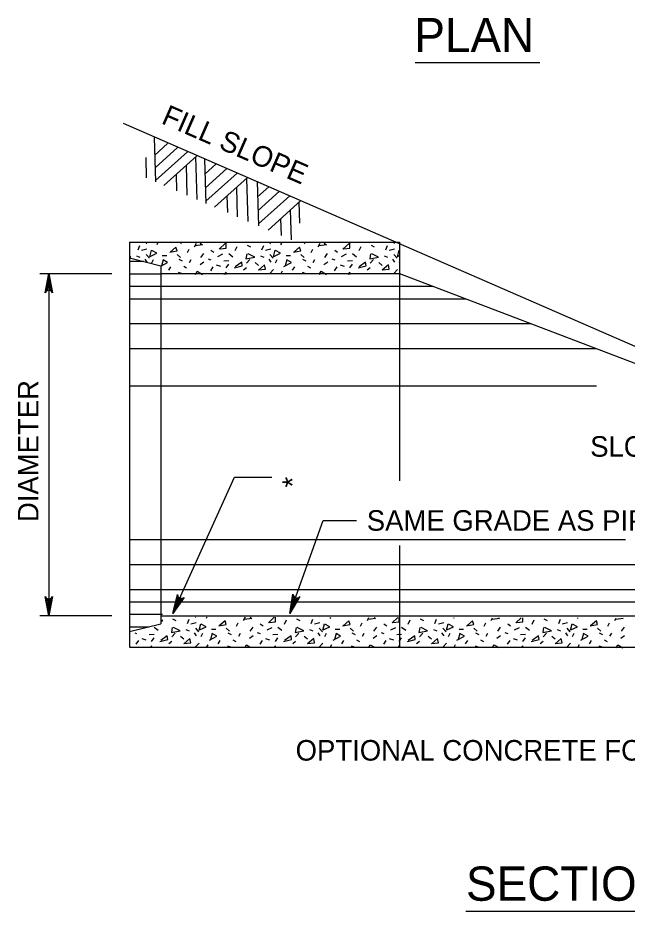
# Model space of a CAD drawing. Extents: x 1 to 8.2, y -2.1 to 8.1.
# Drawn here: x 1.257 to 3.034, y 2.836 to 5.444 of the extents above; entities that cross this region are included whole.
import ezdxf

# ---------------------------------------------------------------- set-up
doc = ezdxf.new("R2010")
doc.units = 0
for name, color, linetype in [('DETL-DIMS', 7, 'Continuous'), ('DETL-LINE', 7, 'Continuous'), ('DETL-NOTE', 7, 'Continuous'), ('DETL-PATT', 7, 'Continuous'), ('DETL-TITL', 7, 'Continuous')]:
    doc.layers.add(name, color=color, linetype=linetype)

msp = doc.modelspace()

# ---------------------------------------------------------------- linework, layer by layer
at = {"layer": 'DETL-DIMS'}
for p, q in [((1.3206, 4.6982), (1.5305, 4.6982)), ((1.347, 4.6982), (1.347, 3.6982)), ((1.7082, 3.7049), (1.8886, 4.1036)), ((1.8886, 4.1036), (1.9971, 4.1036)), ((2.0501, 3.7049), (2.147, 3.977)), ((2.147, 3.977), (2.244, 3.977)), ((1.3206, 3.6995), (1.5305, 3.6995))]:
    msp.add_line(p, q, dxfattribs=at)
for points in [[(1.347, 4.6982), (1.3576, 4.6417), (1.3545, 4.6461), (1.3508, 4.6483), (1.347, 4.649), (1.3432, 4.6483), (1.3394, 4.6461), (1.3364, 4.6417), (1.347, 4.6982), (1.3394, 4.6461), (1.3432, 4.6483), (1.347, 4.6982), (1.347, 4.649), (1.3508, 4.6483), (1.347, 4.6982), (1.3545, 4.6461)], [(1.7082, 3.7049), (1.7219, 3.7608), (1.7228, 3.7555), (1.7253, 3.7519), (1.7285, 3.7498), (1.7322, 3.7488), (1.7366, 3.7493), (1.7412, 3.752), (1.7082, 3.7049), (1.7366, 3.7493), (1.7322, 3.7488), (1.7082, 3.7049), (1.7285, 3.7498), (1.7253, 3.7519), (1.7082, 3.7049), (1.7228, 3.7555)], [(2.0501, 3.7049), (2.0591, 3.7617), (2.0605, 3.7566), (2.0633, 3.7532), (2.0666, 3.7513), (2.0704, 3.7506), (2.0747, 3.7515), (2.079, 3.7546), (2.0501, 3.7049), (2.0747, 3.7515), (2.0704, 3.7506), (2.0501, 3.7049), (2.0666, 3.7513), (2.0633, 3.7532), (2.0501, 3.7049), (2.0605, 3.7566)], [(1.347, 3.6982), (1.3364, 3.7547), (1.3394, 3.7504), (1.3432, 3.7481), (1.347, 3.7475), (1.3508, 3.7481), (1.3545, 3.7504), (1.3576, 3.7547), (1.347, 3.6982), (1.3545, 3.7504), (1.3508, 3.7481), (1.347, 3.6982), (1.347, 3.7475), (1.3432, 3.7481), (1.347, 3.6982), (1.3394, 3.7504)]]:
    msp.add_lwpolyline(points, dxfattribs=at)
at = {"layer": 'DETL-LINE'}
for p, q in [((1.5635, 5.1374), (3.9667, 4.0886)), ((1.5824, 4.7891), (2.3702, 4.7891)), ((1.5824, 4.7891), (1.5824, 4.6982)), ((1.5824, 4.7891), (1.5824, 3.6982)), ((2.3702, 4.7891), (2.3702, 4.0925)), ((1.5824, 4.7437), (1.6733, 4.7209)), ((1.5824, 4.7336), (1.6226, 4.7336)), ((1.6733, 4.7209), (1.6733, 3.6755)), ((1.5824, 4.6982), (1.5824, 4.4435)), ((1.5824, 4.6972), (1.6733, 4.6972)), ((1.6733, 4.6982), (2.3702, 4.6982)), ((2.3702, 4.6982), (3.9667, 4.0886)), ((1.5824, 4.6609), (2.468, 4.6609)), ((1.5824, 4.6245), (2.5633, 4.6245)), ((1.5824, 4.5518), (2.7537, 4.5518)), ((1.5824, 4.4791), (2.9442, 4.4791)), ((1.5824, 4.37), (2.9442, 4.37)), ((1.5824, 3.9214), (3.0294, 3.9214)), ((2.3702, 3.9039), (2.3702, 3.6073)), ((1.5824, 3.8486), (3.1805, 3.8486)), ((1.5824, 3.7759), (3.3316, 3.7759)), ((1.5824, 3.7395), (3.4222, 3.7395)), ((1.5824, 3.7032), (1.6785, 3.7032)), ((1.5824, 3.6982), (1.5824, 3.6073)), ((1.6733, 3.6982), (4.0369, 3.6982)), ((1.5824, 3.6528), (1.6733, 3.6755)), ((1.5824, 3.6668), (1.6386, 3.6668)), ((1.5824, 3.6073), (4.0369, 3.6073))]:
    msp.add_line(p, q, dxfattribs=at)
at = {"layer": 'DETL-PATT'}
for p, q in [((1.6543, 5.0948), (1.658, 4.9657)), ((1.6935, 5.078), (1.6558, 5.0438)), ((1.7219, 5.0659), (1.6571, 5.0069)), ((1.6296, 5.0372), (1.6312, 4.9771)), ((1.7514, 5.0532), (1.6584, 4.9695)), ((1.7782, 5.0418), (1.682, 4.955)), ((1.7751, 5.0391), (1.7789, 4.9139)), ((1.7473, 5.0142), (1.7497, 4.9264)), ((1.8009, 5.032), (1.8053, 4.9026)), ((1.8344, 5.0177), (1.8025, 4.9886)), ((1.7184, 4.9882), (1.7196, 4.9393)), ((1.8659, 5.0042), (1.8038, 4.948)), ((1.8966, 4.991), (1.8052, 4.9089)), ((1.9264, 4.9783), (1.8304, 4.8918)), ((1.9238, 4.9758), (1.9275, 4.8503)), ((1.9546, 4.9662), (1.9586, 4.8369)), ((1.8941, 4.9489), (1.8963, 4.8636)), ((1.989, 4.9514), (1.956, 4.9216)), ((2.0195, 4.9384), (1.9571, 4.8823)), ((1.8665, 4.9235), (1.8676, 4.8759)), ((2.0503, 4.9252), (1.9584, 4.8429)), ((2.0824, 4.9114), (1.9864, 4.825)), ((2.0765, 4.906), (2.0785, 4.845)), ((2.1, 4.9039), (2.1, 4.9039)), ((2.0508, 4.883), (2.0537, 4.7962)), ((2.0231, 4.858), (2.0242, 4.8088)), ((1.6115, 4.7785), (1.6067, 4.7665)), ((1.6325, 4.7865), (1.6308, 4.7845)), ((1.6642, 4.7865), (1.6621, 4.7821)), ((1.7305, 4.7865), (1.7331, 4.7857)), ((1.7716, 4.7761), (1.7772, 4.7865)), ((1.8625, 4.7865), (1.8438, 4.7689)), ((1.8907, 4.7653), (1.8967, 4.7773)), ((1.9256, 4.7809), (1.9352, 4.7761)), ((1.9726, 4.7785), (1.9677, 4.7665)), ((1.9936, 4.7865), (1.9918, 4.7845)), ((2.0253, 4.7865), (2.0231, 4.7821)), ((2.0915, 4.7865), (2.0941, 4.7857)), ((2.1326, 4.7761), (2.1382, 4.7865)), ((2.2235, 4.7865), (2.2048, 4.7689)), ((2.2518, 4.7653), (2.2578, 4.7773)), ((2.2867, 4.7809), (2.2963, 4.7761)), ((2.3336, 4.7785), (2.3288, 4.7665)), ((2.3546, 4.7865), (2.3528, 4.7845)), ((1.6031, 4.7496), (1.6127, 4.746)), ((1.6332, 4.7689), (1.6175, 4.7653)), ((1.6308, 4.7532), (1.6404, 4.7424)), ((1.6777, 4.7508), (1.6909, 4.7508)), ((1.721, 4.7532), (1.7307, 4.7448)), ((1.7511, 4.7592), (1.7559, 4.7689)), ((1.7981, 4.7568), (1.7896, 4.7448)), ((1.8197, 4.7665), (1.8281, 4.7604)), ((1.8534, 4.7544), (1.839, 4.7472)), ((1.8715, 4.7568), (1.8835, 4.7472)), ((1.9641, 4.7496), (1.9738, 4.746)), ((1.9942, 4.7689), (1.9786, 4.7653)), ((1.9918, 4.7532), (2.0014, 4.7424)), ((2.0387, 4.7508), (2.052, 4.7508)), ((2.0821, 4.7532), (2.0917, 4.7448)), ((2.1122, 4.7592), (2.117, 4.7689)), ((2.1591, 4.7568), (2.1507, 4.7448)), ((2.1807, 4.7665), (2.1892, 4.7604)), ((2.2144, 4.7544), (2.2, 4.7472)), ((2.2325, 4.7568), (2.2445, 4.7472)), ((2.3252, 4.7496), (2.3348, 4.746)), ((2.3552, 4.7689), (2.3396, 4.7653)), ((2.3528, 4.7532), (2.3625, 4.7424)), ((1.6272, 4.74), (1.6332, 4.7316)), ((1.6512, 4.7376), (1.6464, 4.7279)), ((1.7258, 4.74), (1.7355, 4.7352)), ((1.7571, 4.7303), (1.762, 4.7388)), ((1.7993, 4.7316), (1.7884, 4.7231)), ((1.8113, 4.7412), (1.8197, 4.7376)), ((1.8354, 4.7231), (1.8474, 4.7195)), ((1.857, 4.7352), (1.8715, 4.7364)), ((1.8642, 4.7147), (1.8715, 4.7255)), ((1.9232, 4.7279), (1.9328, 4.7388)), ((1.9485, 4.7303), (1.9581, 4.7219)), ((1.9882, 4.74), (1.9942, 4.7316)), ((2.0123, 4.7376), (2.0075, 4.7279)), ((2.0869, 4.74), (2.0965, 4.7352)), ((2.1182, 4.7303), (2.123, 4.7388)), ((2.1603, 4.7316), (2.1495, 4.7231)), ((2.1723, 4.7412), (2.1807, 4.7376)), ((2.1964, 4.7231), (2.2084, 4.7195)), ((2.2181, 4.7352), (2.2325, 4.7364)), ((2.2253, 4.7147), (2.2325, 4.7255)), ((2.2842, 4.7279), (2.2939, 4.7388)), ((2.3095, 4.7303), (2.3191, 4.7219)), ((2.3492, 4.74), (2.3552, 4.7316)), ((2.3702, 4.7315), (2.3685, 4.7279)), ((1.697, 4.7075), (1.703, 4.7171)), ((1.7246, 4.7015), (1.7331, 4.6991)), ((1.7403, 4.7195), (1.7487, 4.7147)), ((1.7941, 4.6952), (1.7941, 4.6952)), ((1.8257, 4.7171), (1.8185, 4.7063)), ((1.9148, 4.7087), (1.9232, 4.7159)), ((2.0026, 4.7099), (1.9918, 4.6979)), ((2.0279, 4.7051), (2.0231, 4.6955)), ((2.058, 4.7075), (2.064, 4.7171)), ((2.0857, 4.7015), (2.0941, 4.6991)), ((2.1013, 4.7195), (2.1097, 4.7147)), ((2.1564, 4.6954), (2.1564, 4.6954)), ((2.1564, 4.6954), (2.1564, 4.6954)), ((2.1564, 4.6954), (2.1564, 4.6954)), ((2.1564, 4.6954), (2.1564, 4.6954)), ((2.1868, 4.7171), (2.1795, 4.7063)), ((2.2758, 4.7087), (2.2842, 4.7159)), ((2.3637, 4.7099), (2.3528, 4.6979)), ((1.6769, 3.6816), (1.6792, 3.6864)), ((1.7081, 3.69), (1.7177, 3.6852)), ((1.755, 3.6876), (1.7502, 3.6755)), ((1.7767, 3.6779), (1.7611, 3.6743)), ((1.7753, 3.6948), (1.7743, 3.6936)), ((1.8073, 3.6947), (1.8056, 3.6912)), ((1.8946, 3.6683), (1.8994, 3.6779)), ((1.9151, 3.6852), (1.9201, 3.6944)), ((2.0046, 3.6942), (1.9873, 3.6779)), ((2.0342, 3.6743), (2.0402, 3.6864)), ((2.0691, 3.69), (2.0788, 3.6852)), ((2.1161, 3.6876), (2.1113, 3.6755)), ((2.1377, 3.6779), (2.1221, 3.6743)), ((2.1357, 3.694), (2.1353, 3.6936)), ((2.168, 3.6939), (2.1666, 3.6912)), ((2.2557, 3.6683), (2.2605, 3.6779)), ((2.2761, 3.6852), (2.2807, 3.6936)), ((2.3648, 3.6934), (2.3483, 3.6779)), ((2.3953, 3.6743), (2.4013, 3.6864)), ((2.4302, 3.69), (2.4398, 3.6852)), ((2.4771, 3.6876), (2.4723, 3.6755)), ((2.4988, 3.6779), (2.4831, 3.6743)), ((2.5286, 3.6931), (2.5276, 3.6912)), ((2.6167, 3.6683), (2.6215, 3.6779)), ((2.6372, 3.6852), (2.6413, 3.6928)), ((2.725, 3.6926), (2.7094, 3.6779)), ((2.7563, 3.6743), (2.7623, 3.6864)), ((2.7912, 3.69), (2.8008, 3.6852)), ((2.8381, 3.6876), (2.8333, 3.6755)), ((2.8598, 3.6779), (2.8441, 3.6743)), ((2.8892, 3.6923), (2.8887, 3.6912)), ((2.9777, 3.6683), (2.9825, 3.6779)), ((2.9982, 3.6852), (3.0019, 3.692)), ((1.6544, 3.6655), (1.666, 3.6563)), ((1.7466, 3.6587), (1.7562, 3.6551)), ((1.7743, 3.6623), (1.7839, 3.6515)), ((1.8212, 3.6599), (1.8345, 3.6599)), ((1.8645, 3.6623), (1.8742, 3.6539)), ((1.9416, 3.6659), (1.9331, 3.6539)), ((1.9632, 3.6755), (1.9717, 3.6695)), ((1.9969, 3.6635), (1.9825, 3.6563)), ((2.015, 3.6659), (2.027, 3.6563)), ((2.1076, 3.6587), (2.1173, 3.6551)), ((2.1353, 3.6623), (2.145, 3.6515)), ((2.1823, 3.6599), (2.1955, 3.6599)), ((2.2256, 3.6623), (2.2352, 3.6539)), ((2.3026, 3.6659), (2.2942, 3.6539)), ((2.3243, 3.6755), (2.3327, 3.6695)), ((2.358, 3.6635), (2.3435, 3.6563)), ((2.376, 3.6659), (2.388, 3.6563)), ((2.4687, 3.6587), (2.4783, 3.6551)), ((2.4964, 3.6623), (2.506, 3.6515)), ((2.5433, 3.6599), (2.5565, 3.6599)), ((2.5866, 3.6623), (2.5962, 3.6539)), ((2.6636, 3.6659), (2.6552, 3.6539)), ((2.6853, 3.6755), (2.6937, 3.6695)), ((2.719, 3.6635), (2.7045, 3.6563)), ((2.737, 3.6659), (2.7491, 3.6563)), ((2.8297, 3.6587), (2.8393, 3.6551)), ((2.8574, 3.6623), (2.867, 3.6515)), ((2.9043, 3.6599), (2.9176, 3.6599)), ((2.9476, 3.6623), (2.9573, 3.6539)), ((3.0247, 3.6659), (3.0162, 3.6539)), ((1.5978, 3.6485), (1.6022, 3.6466)), ((1.6082, 3.6262), (1.601, 3.6154)), ((1.6178, 3.6322), (1.6299, 3.6286)), ((1.6395, 3.6442), (1.6539, 3.6454)), ((1.6467, 3.6238), (1.6539, 3.6346)), ((1.7057, 3.637), (1.7153, 3.6479)), ((1.731, 3.6394), (1.7406, 3.631)), ((1.7707, 3.6491), (1.7767, 3.6406)), ((1.7947, 3.6466), (1.7899, 3.637)), ((1.8405, 3.6166), (1.8465, 3.6262)), ((1.8694, 3.6491), (1.879, 3.6442)), ((1.8838, 3.6286), (1.8922, 3.6238)), ((1.9007, 3.6394), (1.9055, 3.6479)), ((1.9428, 3.6406), (1.9319, 3.6322)), ((1.9548, 3.6503), (1.9632, 3.6466)), ((1.9692, 3.6262), (1.962, 3.6154)), ((1.9789, 3.6322), (1.9909, 3.6286)), ((2.0005, 3.6442), (2.015, 3.6454)), ((2.0078, 3.6238), (2.015, 3.6346)), ((2.0667, 3.637), (2.0764, 3.6479)), ((2.092, 3.6394), (2.1016, 3.631)), ((2.1317, 3.6491), (2.1377, 3.6406)), ((2.1558, 3.6466), (2.151, 3.637)), ((2.2015, 3.6166), (2.2075, 3.6262)), ((2.2304, 3.6491), (2.24, 3.6442)), ((2.2448, 3.6286), (2.2533, 3.6238)), ((2.2617, 3.6394), (2.2665, 3.6479)), ((2.3038, 3.6406), (2.293, 3.6322)), ((2.3158, 3.6503), (2.3243, 3.6466)), ((2.3303, 3.6262), (2.3231, 3.6154)), ((2.3399, 3.6322), (2.3519, 3.6286)), ((2.3616, 3.6442), (2.376, 3.6454)), ((2.3688, 3.6238), (2.376, 3.6346)), ((2.4278, 3.637), (2.4374, 3.6479)), ((2.453, 3.6394), (2.4627, 3.631)), ((2.4927, 3.6491), (2.4988, 3.6406)), ((2.5168, 3.6466), (2.512, 3.637)), ((2.5625, 3.6166), (2.5686, 3.6262)), ((2.5914, 3.6491), (2.6011, 3.6442)), ((2.6059, 3.6286), (2.6143, 3.6238)), ((2.6227, 3.6394), (2.6275, 3.6479)), ((2.6648, 3.6406), (2.654, 3.6322)), ((2.6769, 3.6503), (2.6853, 3.6466)), ((2.6913, 3.6262), (2.6841, 3.6154)), ((2.7009, 3.6322), (2.713, 3.6286)), ((2.7226, 3.6442), (2.737, 3.6454)), ((2.7298, 3.6238), (2.737, 3.6346)), ((2.7888, 3.637), (2.7984, 3.6479)), ((2.8141, 3.6394), (2.8237, 3.631)), ((2.8538, 3.6491), (2.8598, 3.6406)), ((2.8778, 3.6466), (2.873, 3.637)), ((2.9236, 3.6166), (2.9296, 3.6262)), ((2.9525, 3.6491), (2.9621, 3.6442)), ((2.9669, 3.6286), (2.9753, 3.6238)), ((2.9837, 3.6394), (2.9886, 3.6479)), ((3.0259, 3.6406), (3.015, 3.6322)), ((1.6973, 3.6178), (1.7057, 3.625)), ((1.7851, 3.619), (1.775, 3.6078)), ((1.8104, 3.6142), (1.8072, 3.6077)), ((1.8682, 3.6105), (1.8766, 3.6081)), ((2.0583, 3.6178), (2.0667, 3.625)), ((2.1462, 3.619), (2.1354, 3.607)), ((2.1714, 3.6142), (2.1678, 3.6069)), ((2.2292, 3.6105), (2.2376, 3.6081)), ((2.4193, 3.6178), (2.4278, 3.625)), ((2.5072, 3.619), (2.4964, 3.6069)), ((2.5325, 3.6142), (2.5285, 3.6061)), ((2.5902, 3.6105), (2.5986, 3.6081)), ((2.7804, 3.6178), (2.7888, 3.625)), ((2.8682, 3.619), (2.8574, 3.6069)), ((2.8935, 3.6142), (2.8891, 3.6054)), ((2.9513, 3.6105), (2.9597, 3.6081))]:
    msp.add_line(p, q, dxfattribs=at)
for points in [[(1.6994, 4.7604), (1.721, 4.764), (1.7174, 4.7749), (1.7006, 4.7604)], [(1.7886, 4.7865), (1.7956, 4.7821), (1.774, 4.7785)], [(1.8462, 4.7701), (1.8642, 4.7725), (1.8642, 4.7865)], [(2.0604, 4.7604), (2.0821, 4.764), (2.0785, 4.7749), (2.0616, 4.7604)], [(2.1496, 4.7865), (2.1567, 4.7821), (2.135, 4.7785)], [(2.2072, 4.7701), (2.2253, 4.7725), (2.2253, 4.7865)], [(1.5837, 4.7455), (1.5862, 4.746), (1.5837, 4.7473)], [(1.6609, 4.7568), (1.6416, 4.7472), (1.6464, 4.7665), (1.6609, 4.758)], [(1.9244, 4.7556), (1.922, 4.7412), (1.9473, 4.746), (1.928, 4.7556)], [(2.0219, 4.7568), (2.0026, 4.7472), (2.0075, 4.7665), (2.0219, 4.758)], [(2.2854, 4.7556), (2.283, 4.7412), (2.3083, 4.746), (2.2891, 4.7556)], [(2.3702, 4.7505), (2.3637, 4.7472), (2.3685, 4.7665), (2.3702, 4.7654)], [(1.6732, 4.7191), (1.6934, 4.7303), (1.6801, 4.7376), (1.6753, 4.7207)], [(1.8883, 4.7147), (1.9112, 4.7207), (1.91, 4.7316), (1.8907, 4.7171)], [(1.9581, 4.7087), (1.9786, 4.7111), (1.9762, 4.7231), (1.9581, 4.7075)], [(2.0327, 4.7183), (2.0544, 4.7303), (2.0411, 4.7376), (2.0363, 4.7207)], [(2.2493, 4.7147), (2.2722, 4.7207), (2.271, 4.7316), (2.2518, 4.7171)], [(2.3191, 4.7087), (2.3396, 4.7111), (2.3372, 4.7231), (2.3191, 4.7075)], [(1.7746, 4.6951), (1.78, 4.7051), (1.7956, 4.6955), (1.7941, 4.6952)], [(1.8642, 4.6952), (1.8642, 4.7015), (1.8576, 4.6952)], [(2.1358, 4.6954), (2.141, 4.7051), (2.1567, 4.6955), (2.1564, 4.6954)], [(2.2253, 4.6954), (2.2253, 4.7015), (2.2189, 4.6954)], [(1.8429, 3.6695), (1.8645, 3.6731), (1.8609, 3.684), (1.8441, 3.6695)], [(1.9339, 3.6944), (1.9392, 3.6912), (1.9175, 3.6876)], [(1.9897, 3.6791), (2.0078, 3.6815), (2.0078, 3.6942)], [(2.2039, 3.6695), (2.2256, 3.6731), (2.222, 3.684), (2.2051, 3.6695)], [(2.2963, 3.6936), (2.3002, 3.6912), (2.2785, 3.6876)], [(2.3507, 3.6791), (2.3688, 3.6815), (2.3688, 3.6934)], [(2.565, 3.6695), (2.5866, 3.6731), (2.583, 3.684), (2.5662, 3.6695)], [(2.6586, 3.6928), (2.6612, 3.6912), (2.6396, 3.6876)], [(2.7118, 3.6791), (2.7298, 3.6815), (2.7298, 3.6926)], [(2.926, 3.6695), (2.9476, 3.6731), (2.944, 3.684), (2.9272, 3.6695)], [(3.021, 3.692), (3.0223, 3.6912), (3.0006, 3.6876)], [(1.7069, 3.6647), (1.7045, 3.6503), (1.7298, 3.6551), (1.7105, 3.6647)], [(1.8044, 3.6659), (1.7851, 3.6563), (1.7899, 3.6755), (1.8044, 3.6671)], [(2.0679, 3.6647), (2.0655, 3.6503), (2.0908, 3.6551), (2.0715, 3.6647)], [(2.1654, 3.6659), (2.1462, 3.6563), (2.151, 3.6755), (2.1654, 3.6671)], [(2.429, 3.6647), (2.4266, 3.6503), (2.4518, 3.6551), (2.4326, 3.6647)], [(2.5264, 3.6659), (2.5072, 3.6563), (2.512, 3.6755), (2.5264, 3.6671)], [(2.79, 3.6647), (2.7876, 3.6503), (2.8129, 3.6551), (2.7936, 3.6647)], [(2.8875, 3.6659), (2.8682, 3.6563), (2.873, 3.6755), (2.8875, 3.6671)], [(1.6708, 3.6238), (1.6937, 3.6298), (1.6925, 3.6406), (1.6732, 3.6262)], [(1.7406, 3.6178), (1.7611, 3.6202), (1.7586, 3.6322), (1.7406, 3.6166)], [(1.8152, 3.6274), (1.8369, 3.6394), (1.8236, 3.6466), (1.8188, 3.6298)], [(2.0318, 3.6238), (2.0547, 3.6298), (2.0535, 3.6406), (2.0342, 3.6262)], [(2.1016, 3.6178), (2.1221, 3.6202), (2.1197, 3.6322), (2.1016, 3.6166)], [(2.1762, 3.6274), (2.1979, 3.6394), (2.1847, 3.6466), (2.1798, 3.6298)], [(2.3929, 3.6238), (2.4157, 3.6298), (2.4145, 3.6406), (2.3953, 3.6262)], [(2.4627, 3.6178), (2.4831, 3.6202), (2.4807, 3.6322), (2.4627, 3.6166)], [(2.5373, 3.6274), (2.5589, 3.6394), (2.5457, 3.6466), (2.5409, 3.6298)], [(2.7539, 3.6238), (2.7768, 3.6298), (2.7756, 3.6406), (2.7563, 3.6262)], [(2.8237, 3.6178), (2.8441, 3.6202), (2.8417, 3.6322), (2.8237, 3.6166)], [(2.8983, 3.6274), (2.92, 3.6394), (2.9067, 3.6466), (2.9019, 3.6298)], [(1.6467, 3.608), (1.6467, 3.6105), (1.6441, 3.608)], [(1.9199, 3.6074), (1.9235, 3.6142), (1.9345, 3.6074)], [(2.0078, 3.6073), (2.0078, 3.6105), (2.0043, 3.6073)], [(2.2805, 3.6067), (2.2845, 3.6142), (2.2968, 3.6066)], [(2.3688, 3.6065), (2.3688, 3.6105), (2.3645, 3.6065)], [(2.6411, 3.6059), (2.6456, 3.6142), (2.6591, 3.6059)], [(2.7298, 3.6057), (2.7298, 3.6105), (2.7247, 3.6057)], [(3.0017, 3.6051), (3.0066, 3.6142), (3.0214, 3.6051)]]:
    msp.add_lwpolyline(points, dxfattribs=at)
at = {"layer": 'DETL-TITL'}
for p, q in [((2.4156, 5.3141), (2.7787, 5.3141)), ((2.5635, 2.8364), (3.6096, 2.8364))]:
    msp.add_line(p, q, dxfattribs=at)

# ---------------------------------------------------------------- texts
at = {"layer": 'DETL-NOTE'}
for s, rotation, p in [('FILL SLOPE', 336.4014, (1.6721, 5.1374)), ('DIAMETER', 90, (1.3167, 3.9723)), ('*', 90, (2.0877, 4.0733))]:
    msp.add_text(s, height=0.06, rotation=rotation, dxfattribs=at).set_placement(p)
for s, p in [('SLOPE', (2.926, 4.1631)), ('SAME GRADE AS PIPE INVERT', (2.2743, 3.947)), ('OPTIONAL CONCRETE FOOTER', (2.0667, 3.2759))]:
    msp.add_text(s, height=0.06, dxfattribs=at).set_placement(p)
at = {"layer": 'DETL-TITL'}
for s, p in [('PLAN', (2.4132, 5.3444)), ('SECTION A-A', (2.5637, 2.8667))]:
    msp.add_text(s, height=0.1, dxfattribs=at).set_placement(p)

doc.saveas('drawing.dxf')
